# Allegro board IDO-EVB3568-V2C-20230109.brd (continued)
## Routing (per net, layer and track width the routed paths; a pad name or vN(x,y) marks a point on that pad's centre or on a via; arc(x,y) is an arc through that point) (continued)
WIFI1T1R_CMD: length 2.2
  TOP w0.127: U18.16 107.66,26.54 R186.2
WIFI1T1R_D0: length 2.4
  TOP w0.127: U18.18 105.86,24.73 105.59,24.99 105.59,26.4 R181.2
WIFI1T1R_D1: length 2.4
  TOP w0.127: R182.2 104.62,26.45 104.62,25.7 104.96,25.37 U18.19
WIFI1T1R_D2: length 2.4
  TOP w0.127: R183.2 109.3,26.25 109.3,25.35 109.46,25.19 U18.14
WIFI1T1R_D3: length 2.4
  TOP w0.127: R184.2 108.66,25.98 108.41,25.73 108.41,25.37 108.56,25.22 U18.15
WIFI1T1R_XTAL_IN: length 8.4
  TOP w0.254: U18.10 112.9,22.22 113.36,22.68 114.69,22.68 C114.1 115.7,23.76 117.04,25.1 117.04,26.24 XT2.3
WIFI1T1R_XTAL_OUT: length 2.1
  TOP w0.254: R191.2 113.87,23.12 U18.11
WIFI_PWREN_L_GPIO0_B7: length 114.9
  TOP w0.127: v1(123.44,42.55) 123.44,40.28 125.78,37.95 125.78,35.04 R207.2 ; J2.114 57.92,52.46 57.61,52.15 56.65,52.15 53.19,48.68 53.19,46.46 53.6,46.04 53.6,45.25 53.44,45.09 53.44,44.83 v1(53.42,44.81)
  BOTTOM w0.127: v1(123.44,42.55) 123.14,42.24 122.38,42.24 121.49,43.13 113.11,43.13 108.79,38.81 105.87,38.81 105.11,38.05 99.64,38.05 99.26,37.67 97.8,37.67 95.3,40.16 95.01,40.46 77.42,40.46 75.26,38.3 74.24,38.3 73.23,37.29 73.23,36.35 66.55,29.67 57.35,29.67 56.59,30.43 53.29,30.43 52.27,31.45 52.27,41.38 53.43,42.54 53.43,44.79 v1(53.42,44.81)
WIFI_REG_ON_H_GPIO3_D5: length 86.9
  TOP w0.127: R196.1 v1(110.85,28.02) 110.85,28.88 108.28,31.45 106.75,31.45 97.35,31.45 97.16,31.64 97.16,42.37 97.35,42.56 v1(97.35,42.65) ; v1(101.55,11.07) 101.73,11.07 102.08,10.72 102.08,9.89 R210.1 ; v1(77.29,60.17) 77.32,60.15 77.67,60.15 78.17,60.65 J2.33
  BOTTOM w0.127: v1(110.85,28.02) 110.21,28.02 106.55,24.36 106.55,17.65 101.55,12.65 v1(101.55,11.07) ; v1(77.29,60.17) 77.55,59.92 77.55,55.62 78.41,54.76 78.41,51.92 79.32,51 79.32,49.23 79.07,48.97 79.07,46.94 83.01,43 96.22,43 96.49,42.72 97.26,42.72 97.33,42.65 v1(97.35,42.65)
WIFI_WAKE_HOST_H_GPIO3_D4: length 70.1
  TOP w0.127: v1(79.68,62.73) 79.68,62.74 79.5,62.74 79.17,62.41 J2.29 ; U18.13 110.36,28.99 108.15,31.19 106.65,31.19 106.65,31.19 105.6,31.19 105.6,31.19 97.24,31.19 96.88,31.56 96.88,43.32 v1(97.15,43.59)
  BOTTOM w0.127: v1(79.68,62.73) 79.19,62.73 77.8,61.34 77.8,55.73 78.66,54.86 78.66,52.04 79.58,51.13 79.58,49.1 79.32,48.84 79.32,47.07 83.13,43.26 96.82,43.26 97.15,43.58 v1(97.15,43.59)
WIFIBT_32KIN_1T1R: length 5.2
  TOP w0.127: U18.24 100.24,22.22 99.77,22.68 C126.2 R204.2 R206.2 R205.2
N17053074: length 3.4
  TOP w0.508: U18.2 C115.2 115.82,15.02 C113.2
N17053234: length 3
  TOP w0.508: J21.2 arc(118.81,14.99) C116.2 arc(117.33,15.01) C113.1
N68563646: length 5.3
  TOP w0.127: U21.1 76.77,32.65 C179.2 77.17,32.02 77.17,30.18 77.04,30.05 XT5.2
N68563661: length 5.5
  TOP w0.127: U21.2 77.42,33.03 C180.2 77.42,32.02 77.42,30.18 77.55,30.05 XT5.1
N69811939: length 4.2
  TOP w0.254: U1.5 69.29,67.89 69.67,67.51 69.67,67.07 69.42,66.82 C12.2 R5.2 71,67.01 R3.1
N69812073: length 0.9
  TOP w0.305: 66.64,65.84 C1.1
N69812091: length 1.8
  TOP w0.305: C1.2 68.45,66.54 69.02,67.11 U1.4
N69812134: length 4.2
  TOP w0.305: U1.6 70,68.39 R4.1
  TOP w0.381: R6.2 R4.1 C8.1
N69812831: length 3.2
  TOP w0.381: C13.1 17.99,25.51 17.27,24.79 16.59,24.79 16.23,25.15
N69812843: length 4
  TOP w0.305: 20.4,28.14 20.02,28.52 U2.6
  TOP w0.381: 20.4,28.14 21.03,27.51 C17.1 R11.1 R12.2
N69812998: length 1.4
  TOP w0.305: C13.2 19.61,27.07 U2.4
N69813915: length 5.1
  TOP w0.127: R13.2 20.4,24.71 20.14,24.97 20.14,25.86 20.52,26.24 20.52,27.38 19.89,28.02 U2.5
N69814410: length 3.3
  TOP w0.381: R15.1 25.61,24.27 U3.5 ; R15.1 C24.1 ; R15.1 R16.2
N69814930: length 1.7
  TOP w0.203: U3.1 29.55,24.27 30.68,23.14 R14.2
N69815076: length 5.7
  TOP w0.127: 76.28,81.48 76.06,81.26 76.06,76.6 76.25,76.4 R10.2
N69815079: length 6.7
  TOP w0.127: R8.2 76.53,80.21 77.29,80.98 77.29,83.01 LED1.1
N69817092: length 6.3
  TOP w0.127: R25.2 54.72,65.68 D5.2 54.06,66.33 54.06,66.51 54.31,66.75 56.16,66.75 57.18,67.77 J4.1
N69817095: length 5.6
  TOP w0.127: J4.2 55.93,67.49 55.45,67.01 54.18,67.01 53.8,66.62 53.8,66.34 D6.2 53.13,65.68 R26.2
N69818339: length 2.8
  TOP w0.254: U8.1 104.26,34.54 103.33,33.6 R58.1
N69818343: length 2.5
  TOP w0.254: U8.7 107.26,34.11 107.01,33.86 R55.1
N69818347: length 2.6
  TOP w0.254: U8.5 106.26,34.51 105.74,33.99 R54.1
N69818991: length 4.5
  TOP w0.254: C44.2 100.27,41.45 U8.39
  TOP w0.381: C44.2 99.32,40.51 R61.1
N69818999: length 2.8
  TOP w0.254: U8.48 102.02,36.95 100.81,35.74 R59.2
N69819001: length 5.2
  TOP w0.254: U8.36 104.26,44.61 104.09,44.78 100.86,44.78 R65.2
N69819016: length 2.5
  TOP w0.254: R73.1 108.26,45.71 U8.28
N69819018: length 3.5
  TOP w0.254: C45.2 99.96,42.2 100.22,41.95 U8.38
N69820056: length 1.1
  TOP w0.381: R45.2 93.86,71.47 U5.3
N69820298: length 1.3
  TOP w0.127: U6.3 91.14,65.29 R51.2
N69820533: length 1.6
  TOP w0.127: R57.2 123.21,22.23 122.93,22.51 U7.4
N69820554: length 1.5
  TOP w0.381: R60.2 123.71,19.81 U7.3
N69820805: length 1.8
  TOP w0.127: R70.2 106.57,9.92 106.42,9.78 U9.4
N69820826: length 2.8
  TOP w0.508: U9.3 109.61,9.15 109.87,9.41 111.83,9.41 R72.2
N69821095: length 2.2
  TOP w0.127: U10.4 97.66,17.69 R77.2
N69821116: length 3.4
  TOP w0.381: U10.3 99.2,13.1 99.7,12.6 R79.2
N69821410: length 2.8
  BOTTOM w0.127: U4.4 121.93,48.93 R36.2 R32.2
N69821431: length 1.9
  BOTTOM w0.381: R33.2 123.01,53.12 122.63,53.5 U4.3
N69829177: length 5.6
  BOTTOM w0.254: Q1.1 115.89,47.93 116.4,48.44 116.92,48.44 117.42,48.95 Q2.3 117.42,49.98 117.49,50.05 R31.1 R30.1 117.5,51.1 R35.2
N69829182: length 11.2
  BOTTOM w0.381: R39.1 115.59,52.46 115.7,52.35 D13.A D11.A 118.19,54.31 117.42,55.07 R37.1 ; R37.1 117.41,57.8 R40.2 ; R37.1 117.44,57.8 R38.2
N69829189: length 15.9
  TOP w0.254: v1(112.03,53.36) 112.03,51.8 117.1,46.73 117.46,46.73 117.51,46.77 v1(117.51,46.81)
  BOTTOM w0.254: R35.1 118.52,50.06 118.19,49.73 118.19,48.34 117.92,48.07 Q2.1 117.92,47.19 117.55,46.81 v1(117.51,46.81)
  BOTTOM w0.508: R39.2 C35.2 R41.2 v1(112.03,53.36)
N69844387: length 1.9
  TOP w0.381: C63.1 128.82,60.91 127.86,60.91 R80.2 R83.2
N69844453: length 6.5
  TOP w0.203: J11.1 126.44,65.23 127.15,64.51 D29.2 127.2,63.65 127.2,62.71 C65.2 127.01,62.51 127.01,61.85 R83.1 126.49,61.77 126.14,61.42 C64.1
N69844782: length 10.9
  TOP w0.203: J10.2 121.11,83.78 121.11,83.26 119.84,81.99 119.84,77.04 120.6,76.28 D27.2 120.57,75.84 R82.2
N69844789: length 3.3
  TOP w0.203: R84.2 116.76,75.84 D28.2 116.79,77.26 J10.3
N69846177: length 0.9
  TOP w0.203: R87.1 C72.1
N69846180: length 16
  TOP w0.254: U11.7 113.41,65.48 114.3,64.59 115.75,64.59 116.38,65.23 116.38,66.88 116.23,67.03 116.23,72.19 116.69,72.64 116.69,73.41 116.43,73.66 115.47,73.66 114,75.13 R87.2
N69846237: length 0.9
  TOP w0.203: R88.1 C75.1
N69846239: length 12.6
  TOP w0.203: R88.2 117.81,74.5 117.08,73.77 117.08,72.48 116.59,71.98 116.59,67.21 116.76,67.03 116.76,65.51 117.3,64.97 117.68,64.97 118.19,65.48 118.95,65.48
N69846282: length 1.9
  TOP w0.381: C71.2 111.14,64.21 U11.8
N69846442: length 31.7
  TOP w0.127: Q14.3 85.69,65.54 86.76,64.47 v1(86.76,63.58) ; U11.5 112.22,68.02 v1(111.71,68.53)
  BOTTOM w0.127: v1(111.71,68.53) 111.71,68.25 109.07,65.61 103.23,65.61 102.34,64.72 96.06,64.72 94.56,63.22 87.12,63.22 v1(86.76,63.58)
N69846447: length 40.7
  TOP w0.127: v1(117.68,67.89) 117.81,68.02 118.95,68.02 ; Q15.3 84.11,65.62 85.2,64.53 85.2,63.33 85.23,63.31 v1(85.23,63.28)
  BOTTOM w0.127: v1(85.23,63.28) 85.55,62.97 94.69,62.97 96.19,64.47 102.46,64.47 103.35,65.35 109.19,65.35 111.99,68.15 117.42,68.15 v1(117.68,67.89)
N69846810: length 2.1
  TOP w0.381: U11.3 111.27,70.56 L11.1
N69846813: length 2.3
  TOP w0.381: L12.1 111.65,73.1 U11.1
N69846816: length 2.4
  TOP w0.203: L13.1 120.22,71.2 119.58,70.56 118.95,70.56
N69846819: length 2.3
  TOP w0.203: L14.1 120.09,72.59 119.58,73.1 118.95,73.1
N69847759: length 6.8
  TOP w0.254: D42.C 73.71,71.65 73.25,71.65 72.85,71.25 71.32,71.25 v1(71.3,71.27) ; R104.2 v1(69.04,70.97)
  TOP w0.305: R106.1 71.17,71.4 v1(71.3,71.27)
  BOTTOM w0.254: v1(69.04,70.97) 69.44,71.37 71.07,71.37 71.15,71.3 71.27,71.3 v1(71.3,71.27)
N69853352: length 4.1
  BOTTOM w0.127: R392.2 22,52.56 22.28,52.28 22.28,50.33 22.22,50.27 21.82,50.27 21.41,49.86 Q13.3
N69854514: length 0.9
  BOTTOM w0.127: Q13.1 20.82,50.79 20.07,50.79 R393.1
N69857283: length 3
  TOP w0.381: R172.1 R173.2 54.81,21.41 55.07,21.67 55.32,21.67 55.73,22.08 U15.4
N69857307: length 3.7
  TOP w0.381: R175.1 60.91,21.54 60.85,21.6 U16.4 ; R175.1 C108.2 ; R175.1 R176.2
N69857397: length 3
  TOP w0.381: U17.4 66.38,21.67 66.12,21.41 R179.2 R177.1
N69863572: length 2.3
  TOP w0.254: R191.1 C117.2 115.55,25.53 XT2.1
N69863896: length 4.2
  TOP w0.127: U18.34 102.26,12.59 100.69,11.02 R209.2 R210.2
N69864199: length 1.9
  TOP w0.381: R208.2 99.87,17.76 99.91,17.72 U18.29
N69864441: length 2.4
  TOP w0.127: U18.12 111.26,25.29 110.85,25.7 R196.2
N69864462: length 6.5
  TOP w0.508: C128.2 v1(99.77,23.7) 100.35,23.12 U18.23
  BOTTOM w0.508: v1(99.77,23.7) 99.9,23.83 v1(99.9,27.13) v1(99.9,27.89)
N69866041: length 3.3
  TOP w0.508: R207.1 R203.1 124.41,33.22 124.52,33.11 C124.1 123.34,32.72 Q10.1
N69873113: length 7.6
  TOP w0.381: C142.2 33.1,71.96 v1(33.22,72.09)
  BOTTOM w0.508: J22.1 32.97,72.34 v1(33.22,72.09)
N69883193: length 8.9
  TOP w0.508: C166.2 50.67,68.55 50.67,73.2 v1(51.12,73.65)
  BOTTOM w0.508: v1(51.12,73.65) 49.81,72.34 J23.1
N69887530: length 3.9
  BOTTOM w0.127: R345.2 96.98,54.24
  BOTTOM w0.508: R343.1 C207.1 ; C207.1 97.92,53.35 98.43,52.84 U22.5 ; C207.1 96.98,54.24
N69887600: length 1.4
  BOTTOM w0.127: R344.2 101.55,52.89 U22.1
N69896427: length 2.5
  TOP w0.508: J26.8 116.9,52 116.41,51.51 R333.1
N69897118: length 3.5
  TOP w0.508: J26.22 108.1,52.15 108.61,51.64 109.17,51.64 109.68,51.13 R337.1
N69899428: length 34.1
  TOP w0.305: J26.42 100.1,55.3 100.61,55.8 107.85,55.8 108.41,55.24 109.65,55.24 110.69,54.2 110.69,50.27 115.01,45.95 115.01,45.95 v1(115.04,45.91) ; LED2.2 123.19,48.37 122.61,47.79 v1(122.61,47.34)
  BOTTOM w0.305: v1(122.61,47.34) 122.61,46.79 121.62,45.8 115.16,45.8 v1(115.04,45.91)
N69899460: length 3
  TOP w0.508: R342.1 122.57,49.79 122.76,49.97 LED2.1
N69910248: length 16.6
  TOP w0.127: v1(128.6,86.69) 128.47,86.82 122.89,86.82 122,85.93 122,83.03 120.9,81.94 120.9,81.1 122.22,79.78 D71.1 122.22,78.59 R330.2
  BOTTOM w0.127: v1(128.6,86.69) 128.88,86.41 SW1.3
N69911722: length 4.1
  TOP w0.508: U12.3 88.28,24.65 89.97,22.96 R99.2
N69911786: length 10.2
  TOP w0.254: 85.04,9.86 J13.17
  TOP w0.508: 85.04,9.86 85.04,10.24 85.8,11 89.81,11 90.32,11.51 C78.2 90.32,13.4 R413.2 R415.2
N69922645: length 2
  TOP w0.508: R117.2 30.49,17.42 U13.3
N69927197: length 1.7
  TOP w0.381: Q8.3 28.23,10.91 28.42,10.72 28.42,10.08 R136.2
N69927388: length 1.1
  TOP w0.305: Q8.1 30.86,11.13 R137.1
N70033042: length 1.5
  TOP w0.127: Q15.1 81.85,64.53 81.72,64.66 R89.2
N70033056: length 1.4
  TOP w0.127: Q14.1 84.72,64.25 84.31,64.66 R90.2
N70059784: length 7.5
  TOP w0.381: v1(20.4,30.28) 20.4,29.57 C258.2 21.18,29.54 R409.2 R408.2
  BOTTOM w0.305: v1(20.4,30.28) 20.4,33.2 20.09,33.51 J15.17
N70064377: length 26.8
  TOP w0.127: v1(88.24,85.42) 85.06,82.25 81.99,82.25 80.31,80.57 78.82,80.57 77.29,79.04 77.29,72.92 77.01,72.64 75.93,72.64 75.69,72.41 75.69,71.7 76.3,71.09 D96.1 76.3,70.49 76.53,70.27 76.53,69.08 76.47,69.02 R412.2
  BOTTOM w0.127: SW2.3 88.24,86.33 v1(88.24,85.42)

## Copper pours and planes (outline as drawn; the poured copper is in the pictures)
GND on TOP (solid shape): 36.54,38.51 36.44,38.51 36.35,38.41 32.95,38.41 32.95,42.06 36.54,42.06
GND on TOP (solid shape): 61.82,38.28 58.22,38.28 58.22,41.88 58.52,41.88 58.52,41.93 61.82,41.93
GND on TOP (solid shape): 67.96,77.21 67.96,76.75 66.3,76.75 66.26,76.79 66.26,77.38 66.39,77.51 67.65,77.51
GND on TOP (solid shape): 12.51,17.49 12.51,17.04 11.08,17.04 10.82,17.31 10.82,17.58 12.07,17.58 12.07,17.72 12.28,17.72
GND on TOP (solid shape): 43.79,67.39 44.02,67.39 44.02,67.12 43.95,67.12 43.95,66 42.82,66 42.82,67.12 42.75,67.12 42.75,67.39 42.98,67.39 43.38,67.79
GND on TOP (solid shape): 60.37,79.02 60.37,78.66 60.36,78.65 60.19,78.65 60.19,76.79 59.8,76.79 59.8,78.65 59.63,78.65 59.63,78.88 59.97,79.22 60.17,79.22
GND on TOP (solid shape): 66.71,36.83 66.71,35.66 66.39,35.34 65.78,35.34 65.74,35.39 65.74,35.98 65.64,36.01 65.64,36.19 65.74,36.19 65.74,37.05 66.5,37.05
GND on TOP (solid shape): 33.65,34.87 34.24,34.87 34.25,34.87 34.25,33.68 34.21,33.64 33,33.64 32.85,33.78 32.85,34.83 32.9,34.87 33.48,34.87 33.48,34.97 33.65,34.97
GND on TOP (solid shape): 54.43,32.33 55.01,32.33 55.05,32.29 55.05,31.23 54.84,31.23 54.84,30.25 54.66,30.25 54.19,30.72 54.19,31.53 54.28,31.53 54.28,32.43 54.43,32.43
GND on TOP (solid shape): 41.91,68.41 41.99,68.41 41.99,68.15 41.38,68.15 41.38,68.19 41.37,68.26 41.35,68.33 41.35,68.39 41.41,68.39 41.41,69.8 41.91,69.8
GND on TOP (solid shape): 61.86,79.03 61.86,78.85 61.74,78.73 61.74,78.65 61.69,78.65 61.69,76.79 61.3,76.79 61.3,78.65 61.14,78.65 61.13,78.66 61.13,79.02 61.33,79.22 61.67,79.22
GND on TOP (solid shape): 43.6,39.35 43.6,38.57 42.61,38.57 42.49,38.69 42.49,39.35 43.3,39.35 43.3,39.56 43.6,39.56
GND on TOP (solid shape): 63.37,79.02 63.37,78.84 63.24,78.71 63.24,78.65 63.19,78.65 63.19,76.79 62.8,76.79 62.8,78.65 62.75,78.65 62.75,78.73 62.62,78.85 62.62,79 62.84,79.22 63.17,79.22
GND on TOP (solid shape): 77.29,17.4 77.35,17.49 77.47,17.47 77.93,17.01 77.93,14.56 77.42,14.56 77.29,14.69
GND on TOP (solid shape): 13.07,17.91 14.45,17.91 14.45,17.81 14.41,17.81 14.31,17.78 14.22,17.74 13.02,17.74 12.51,18.25 12.07,18.25 12.07,18.39 10.82,18.39 10.82,18.79 10.96,18.92 12.06,18.92
GND on TOP (solid shape): 28.13,56.1 28.07,56.03 27.75,56.35 26.92,56.35 26.83,56.41 26.85,56.52 27.27,56.94 27.27,60.37 28.13,60.37
GND on TOP (solid shape): 29.27,43.97 29.27,43.8 29.46,43.61 29.46,42.74 29.4,42.65 29.29,42.67 29.25,42.71 28.54,42.71 28.54,43.92 28.56,43.92 28.56,44.11 29.13,44.11
GND on TOP (solid shape): 43.98,12.56 44.03,12.53 44.02,12.47 44,12.45 44,12.23 43.96,12.23 43.96,10.27 44,10.27 44,10.01 43.71,9.72 43.53,9.91 43.53,10.27 43.57,10.27 43.57,12.26 43.87,12.56
GND on TOP (solid shape): 98.62,25.07 98.6,25.07 98.6,24.97 98.5,24.97 98.5,24.21 98.6,24.21 98.6,24.08 98.5,24.08 98.5,23.32 98.6,23.32 98.6,23.06 98.5,23.06 98.5,22.3 98.6,22.3 98.6,22.14 97.73,22.14 97.28,22.59 97.28,25.07 97.4,25.18 98.62,25.18
GND on TOP (solid shape): 101.04,73.98 101.13,73.91 101.11,73.8 100.74,73.43 100.74,73.32 100.7,73.32 100.7,71.67 100.63,71.59 100.31,71.59 100.31,73.32 100.27,73.32 100.27,73.74 100.52,73.98
GND on TOP (solid shape): 109.79,11.78 109.79,10.6 109.69,10.5 109.29,10.5 109.26,10.47 109.2,10.46 109.17,10.51 109.17,11.25 109.07,11.25 109.07,11.35 108.86,11.35 108.86,11.62 108.82,11.65 108.82,12.11 109.45,12.11
GND on TOP (solid shape): 48.83,14.7 48.79,14.62 48.76,14.53 48.75,14.51 48.57,14.33 47.42,14.33 47.42,14.42 46.46,14.42 46.46,13.52 46.3,13.52 46.3,13.61 45.69,13.61 45.69,14.4 45.68,14.41 45.68,14.57 45.78,14.67 46.98,14.67 47.4,15.09 48.83,15.09
GND on TOP (solid shape): 80.86,17.11 80.92,17.21 81.03,17.18 81.1,17.12 81.1,13.43 81.6,12.94 81.48,12.82 81.48,12.74 81.43,12.74 81.43,10.74 81.03,10.74 81.03,12.74 80.86,12.74 80.86,12.74
GND on TOP (solid shape): 107.59,73.93 107.69,73.86 107.67,73.75 107.23,73.32 107.21,73.32 107.21,71.36 107.24,71.36 107.24,70.96 107.02,70.96 107.02,71.46 106.81,71.67 106.81,73.32 106.78,73.32 106.78,73.76 106.94,73.93
GND on TOP (solid shape): 26.71,43.92 27.48,43.92 27.48,43.1 27.58,43.1 27.58,42.95 27.48,42.95 27.48,42.11 26.9,42.11 26.25,42.76 26.25,43.84 26.29,43.92 26.38,43.94 26.5,43.92 26.63,43.94 26.63,43.94 26.71,43.94
GND on TOP (solid shape): 33.39,52.11 33.87,51.63 34,51.63 34.76,50.86 35.2,50.86 35.25,50.81 35.27,50.7 35.18,50.63 34.26,50.63 34.26,50.88 34.16,50.88 34.16,50.98 33.32,50.98 33.32,51.78 33.19,51.78 33.19,52.17 33.25,52.17
GND on TOP (solid shape): 85.26,54.5 85.29,54.39 85.19,54.33 81.59,54.33 81.59,54.28 81.25,54.28 81.25,54.33 80.69,54.33 80.68,54.71 80.71,54.78 80.78,54.81 84.96,54.81
GND on TOP (solid shape): 31.86,46.31 31.98,46.23 32.11,46.19 32.16,46.18 32.16,46.07 32.56,45.67 32.62,45.67 32.62,45.03 31.8,45.03 31.8,45.84 31.56,45.84 31.47,45.9 31.49,46.01 31.82,46.34
GND on TOP (solid shape): 59.16,51.87 59.19,51.83 59.19,51.5 59.12,51.42 59.12,51.3 58.91,51.3 58.91,50.5 58.12,50.5 58.12,50.44 57.51,50.44 57.29,50.66 56.54,50.66 56.45,50.73 56.47,50.84 56.55,50.91 57.39,50.91 58.65,52.17 59.16,52.17
GND on TOP (solid shape): 120.55,81.64 120.61,81.65 120.64,81.6 120.64,80.99 121.73,79.89 121.73,79.19 121.96,79.19 121.96,79.04 120.81,79.04 120.81,77.32 120.75,77.22 120.64,77.24 120.52,77.36 120.52,81.61
GND on TOP (solid shape): 38.99,70.02 39.02,69.91 38.92,69.85 38.5,69.85 38.5,68.39 38.56,68.39 38.56,68.33 38.54,68.26 38.53,68.19 38.52,68.15 37.92,68.15 37.92,68.41 37.99,68.41 37.99,69.72 37.29,69.72 37.29,70.6 37.37,70.69 38.32,70.69
GND on TOP (solid shape): 45.09,52.17 45.23,52.17 45.36,52.07 46.16,51.27 46.16,50.76 46.1,50.66 45.99,50.69 44.67,52 44.65,52.11 44.75,52.17 44.75,52.17 44.75,54.29 45.09,54.29
GND on TOP (solid shape): 49.82,36.29 49.82,30.52 50.23,30.12 50.23,28.77 50.51,28.49 50.5,28.46 50.51,28.31 50.56,28.16 50.58,28.13 47.87,25.42 47.76,25.4 47.7,25.49 47.7,25.88 48.74,26.92 48.74,37.2 48.91,37.2
GND on TOP (solid shape): 121.92,40.78 122.04,40.8 122.1,40.7 122.1,39.64 123.01,38.73 123.01,38.4 122.98,38.4 122.98,38.31 122.98,38.3 122.89,38.3 122.89,37.54 122.94,37.54 122.94,36.99 122.85,36.91 122.72,36.91 122.72,37.07 122.62,37.07 122.46,37.24 121.37,37.24 121.37,40.22
GND on TOP (solid shape): 66.71,38.38 66.71,38.29 66.71,38.2 66.71,38.2 66.71,37.58 65.82,37.58 65.74,37.66 65.74,38.18 65.64,38.18 65.64,38.27 65.06,38.27 65.03,38.3 65.02,38.35 65.07,38.38 66.54,38.38 66.54,38.6 66.71,38.6
GND on TOP (solid shape): 97.42,34.23 97.48,34.32 97.6,34.3 98.3,33.59 98.3,32.14 98.29,32.13 98.26,31.99 98.27,31.84 98.26,31.75 98.18,31.71 97.46,31.71 97.42,31.75
GND on TOP (solid shape): 47.38,59.14 47.41,59.13 47.53,59.05 47.68,59 47.72,59 47.72,58.92 46.03,57.23 45.91,57.23 45.87,57.26 45.88,57.32 47.07,58.52 47.07,59.02 47.11,59.02 47.24,59.06 47.34,59.13
GND on TOP (solid shape): 50.2,59.17 50.23,59.16 50.33,59.11 50.43,59.07 50.48,59.07 50.48,58.97 47.26,55.76 47.19,55.76 47.15,55.79 47.16,55.85 49.84,58.53 49.84,59.01 49.89,59.02 50.04,59.06 50.17,59.16
GND on TOP (solid shape): 73.84,60.37 74.63,60.37 74.7,59.95 74.67,59.87 74.6,59.83 73.51,59.83 73.43,59.87 73.42,59.97 73.45,60.11 73.44,60.25 73.44,60.26 73.44,60.37 73.5,60.37 73.5,62.29 73.84,62.29
GND on TOP (solid shape): 77.44,29.78 77.96,29.78 77.96,29.04 79.1,29.04 79.19,28.98 79.17,28.87 77.79,27.49 77.79,23.44 77.72,23.35 77.61,23.37 75.48,25.51 75.48,29.04 76.72,29.04 76.72,29.78 77.15,29.78 77.29,29.92
GND on TOP (solid shape): 102.21,47.42 102.21,46.71 102.06,46.71 102.06,46.81 101.3,46.81 101.3,46.71 101.2,46.71 101.2,45.8 100.57,45.8 100.57,45.94 98.72,45.94 98.72,45.82 98.4,45.5 98.38,45.5 98.27,45.49 98.17,45.45 98.07,45.45 98.02,45.54 98.02,45.57 100,47.55 102.08,47.55
GND on TOP (solid shape): 17.68,21.44 17.74,21.53 17.85,21.51 18.03,21.34 22.86,21.34 22.86,21.15 23.11,20.9 23.13,20.79 23.03,20.73 21.84,20.73 21.73,20.62 21.59,20.62 21.59,18.95 18.55,18.95 18.31,19.19 18.31,20.71 17.68,21.35
GND on TOP (solid shape): 48.8,59.14 48.83,59.13 48.93,59.07 49.04,59.03 49.08,59.02 49.08,58.85 46.73,56.5 46.62,56.5 46.53,56.56 46.55,56.67 48.48,58.6 48.48,59 48.52,59.01 48.65,59.05 48.77,59.13
GND on TOP (solid shape): 66.81,19.39 67.76,19.39 67.76,19.66 68.25,20.14 68.78,20.14 68.78,20.24 68.89,20.24 68.89,20.11 69.69,20.11 69.98,19.83 69.98,18.93 69.34,18.3 69.34,17.2 69.28,17.1 69.17,17.13 67.75,18.54 66.15,18.54 65.81,18.88 65.81,20.19 66.5,20.19 66.5,20.29 66.59,20.29 66.59,20.38 66.81,20.38
GND on TOP (solid shape): 72.25,54.1 72.31,54.19 72.42,54.17 72.54,54.06 72.59,52.37 72.59,52.17 73.16,52.17 73.16,51.21 74.45,49.92 75.06,49.92 75.06,49.18 75,49.09 74.89,49.11 72.19,51.81 72.19,52.23 72.26,52.32 72.25,52.39
GND on TOP (solid shape): 116.74,38.78 116.74,38.64 116.68,38.55 116.57,38.57 115.43,39.71 114.67,39.71 114.63,39.75 114.63,40.34 114.53,40.34 114.53,40.43 113.57,40.43 113.57,40.35 113.2,40.35 113.15,40.3 113.12,40.28 112.99,40.28 112.95,40.31 112.96,40.37 113.31,40.72 114.8,40.72
GND on TOP (solid shape): 16.57,13.17 18.14,11.61 18.15,11.55 18.11,11.52 18.05,11.52 17.54,11.01 15.08,11.01 14.91,11.17 14.68,11.22 14.65,11.24 14.63,11.27 14.63,12.76 15.48,12.76 15.48,14.67 15.87,15.07 15.87,15.34 16.24,15.34 16.24,15.43 16.57,15.43
GND on TOP (solid shape): 48.64,11.51 47.83,11.51 47.83,11.46 47.74,11.46 47.7,11.41 47.57,11.41 47.57,11.51 46.79,11.51 46.74,11.41 46.56,11.41 46.56,11.51 45.8,11.51 45.8,11.41 45.7,11.41 45.7,10.8 45.64,10.75 45.59,10.73 45.54,10.72 45.45,10.73 45.4,10.81 45.4,11.62 46.19,12.41 46.19,12.56 47.42,12.56 47.42,12.77 48.64,12.77
GND on TOP (solid shape): 57.33,67.35 57.42,67.29 57.4,67.17 56.96,66.73 56.96,63.84 56.91,63.75 56.81,63.75 56.77,63.77 56.71,63.79 56.18,64.31 56.18,66.16 55.22,66.16 55.22,65.94 55.07,65.94 55.07,66.32 54.45,66.32 54.35,66.42 54.42,66.48 56.27,66.48 57.13,67.35
GND on TOP (solid shape): 61.04,31.53 61.15,31.55 61.21,31.46 61.21,29.56 61.61,29.16 62.31,29.16 62.5,29.34 63.19,29.34 64.21,28.32 64.21,27.95 64.15,27.86 64.04,27.88 63.48,28.44 55.9,28.44 55.52,28.06 55.33,28.06 55.33,28.67 55.69,29.02 58.99,29.02 60.41,30.45 60.41,30.9
GND on TOP (solid shape): 63.34,13.21 63.42,13.16 63.48,13.08 63.56,13.01 63.56,12.87 63.52,12.87 63.52,10.91 63.56,10.91 63.56,10.59 63.26,10.3 63.15,10.28 63.09,10.37 63.09,10.91 63.13,10.91 63.13,12.87 63.12,12.87 63.09,12.93 63.21,13.05 63.21,13.14 63.26,13.18
GND on TOP (solid shape): 126,49.93 127.18,49.93 127.18,49.88 127.42,49.65 127.44,49.54 127.35,49.48 126.05,49.48 126.05,49.34 125.7,49.34 125.61,49.4 125.63,49.51 125.75,49.7 125.77,49.93 125.77,49.95 125.88,50.06 126,50.06
GND on TOP (solid shape): 70.4,70.95 70.52,70.82 70.52,69.42 69.85,68.75 69.02,68.75 68.96,68.74 68.89,68.73 68.58,68.73 68.58,67.17 68.09,66.69 68.09,66.32 67.11,66.32 67.11,67.33 67.29,67.51 67.83,67.51 67.87,67.56 67.97,67.56 67.97,67.66 68,67.68 68,68.08 67.97,68.1 67.97,68.14 68.07,68.24 68.07,68.65 68.08,68.66 68.08,68.84 68.1,68.84 68.1,68.94 68.2,68.94 68.2,69.6 69.05,69.6 69.93,70.48 69.93,71.09 70.17,71.33 70.4,71.33
GND on TOP (solid shape): 121.14,75.36 121.23,75.36 121.23,75.26 121.95,75.26 121.95,74.3 122.13,74.11 122.13,74.09 122.13,74.01 122.15,73.93 122.13,73.84 122.05,73.8 121.29,73.8 120.96,74.13 120.15,74.13 120.07,74.17 120.05,74.26 120.06,74.33 120.06,74.46 120.06,75.38 121.14,75.38
GND on TOP (solid shape): 45.07,18.05 45.16,18 45.15,17.89 44.93,17.36 45.03,16.8 45.03,16.71 44.97,16.66 44.89,16.62 44.79,16.72 44.09,16.72 44.09,17.13 45.01,18.05
GND on TOP (solid shape): 67.82,75.85 67.82,74.85 67.93,74.85 68.03,74.79 68,74.67 67.83,74.5 67.32,74.5 67.32,73.25 67.52,73.25 67.52,71.8 67.45,71.71 67.34,71.73 67.16,71.92 67.16,74.91 66.29,75.79 66.26,75.9 66.36,75.96 67.71,75.96
GND on TOP (solid shape): 29.13,60.3 29.15,60.29 29.15,57.24 29.81,56.58 29.84,56.48 29.77,56.41 29.63,56.34 29.52,56.22 29.3,56.22 29.11,56.03 29.02,56 28.95,56.05 28.84,56.19 28.7,56.28 28.66,56.29 28.66,60.29 28.7,60.33 28.83,60.37 29,60.37
GND on TOP (solid shape): 68.1,80.3 68.17,80.39 68.28,80.37 69.73,78.92 71.05,78.92 71.25,78.72 71.28,78.63 71.23,78.55 71.14,78.5 71.07,78.42 70.41,78.42 70.41,77.55 70.28,77.55 70.28,77.65 69.52,77.65 69.52,77.55 69.42,77.55 69.42,77.5 68.75,77.5 68.75,77.53 68.47,77.81 68.47,78.39 68.02,78.84 68.02,79.22 68.1,79.22
GND on TOP (solid shape): 37.65,38.28 37.71,38.37 37.82,38.35 38.35,37.82 38.77,37.82 38.77,37.27 38.73,37.19 38.65,37.17 38.41,37.16 38.21,37.03 38.2,37.02 38.13,37.02 38.13,37.12 37.31,37.93 37.29,38.04 37.38,38.1 37.65,38.1
GND on TOP (solid shape): 73.99,44.56 74.02,44.61 74.08,44.6 74.1,44.57 74.1,43.91 74.41,43.6 74.41,43.58 74.44,43.32 74.6,43.12 74.65,43.05 74.62,42.96 74.13,42.48 74.13,40.71 74.86,39.98 74.86,39.84 74.51,39.84 74.16,39.49 74.05,39.47 73.99,39.56
GND on TOP (solid shape): 30.22,14.04 31.29,14.04 31.39,13.98 31.36,13.86 31.27,13.74 31.23,13.59 31.22,13.55 30.22,13.55 30.22,13.48 30.15,13.39 30.04,13.41 29.4,14.06 29.37,14.06 29.37,14.2 28.1,14.2 28.01,14.26 28.03,14.37 28.33,14.67 30.22,14.67
GND on TOP (solid shape): 87.61,51.52 87.88,51.33 88.2,51.35 88.3,51.34 88.34,51.26 88.34,42.73 88.24,42.62 86.2,42.62 85.8,42.22 85.8,41.37 86.2,40.97 88.21,40.97 88.21,40.84 85.97,40.84 85.73,40.6 85.62,40.58 85.56,40.68 85.56,42.35 84.8,43.11 84.8,48.86 87.46,51.52
GND on TOP (solid shape): 27.75,55.59 27.75,55.33 27.7,55.24 27.6,55.24 27.07,55.17 26.93,54.65 26.94,54.62 26.65,54.33 25.64,54.33 25.56,54.37 25.54,54.45 25.55,54.53 25.54,54.6 25.54,54.63 26.73,55.82 27.52,55.82
GND on TOP (solid shape): 33.4,23.24 34.21,23.24 34.21,23 34.44,22.77 34.47,22.7 34.44,22.62 34.32,22.48 34.27,22.29 34.27,22.25 32.29,22.25 32.04,21.99 31.38,21.99 31.38,21.41 31.22,21.25 30.99,21.25 30.99,21.75 31.16,21.75 31.16,23.27 31.22,23.37 31.33,23.34 31.44,23.24 32.29,23.24 32.43,23.38 32.47,23.38 32.47,23.42 32.54,23.49 32.54,23.57 33.4,23.57
GND on TOP (solid shape): 84.87,74.34 84.95,74.37 85.03,74.33 85.09,74.26 85.16,74.2 85.2,74.13 85.17,74.05 85,73.87 85,73.6 84.83,73.6 84.83,71.64 85.01,71.64 85.01,71.43 85.16,71.28 85.16,71.2 84.72,71.2 84.72,70.73 84.52,70.73 84.52,71.15 84.34,71.15 84.25,71.21 84.26,71.32 84.26,71.64 84.44,71.64 84.44,73.6 84.28,73.6 84.28,73.76
GND on TOP (solid shape): 60.09,52.39 60.08,52.32 60.17,52.22 60.17,52.1 60.29,51.98 60.29,51.59 60.77,51.11 60.8,51.03 60.75,50.95 60.72,50.93 60.69,50.91 60.66,50.89 60.62,50.91 60.33,51.02 60.03,50.93 59.92,50.92 59.86,51.01 59.86,51.3 59.73,51.3 59.73,52.05 59.69,52.09 59.69,52.23 59.76,52.32 59.75,52.39 59.75,54.29 60.09,54.29
GND on TOP (solid shape): 85.57,65.04 85.63,65.13 85.74,65.11 86.5,64.36 86.5,63.97 86.32,63.75 86.3,63.46 86.28,63.37 86.2,63.33 85.71,63.33 85.7,63.38 85.62,63.56 85.47,63.7 85.47,64.64 85.37,64.74 85.35,64.85 85.44,64.92 85.57,64.92
GND on TOP (solid shape): 39.74,55.49 39.83,55.5 39.86,55.5 40.85,54.5 40.87,54.39 40.78,54.33 39.59,54.33 39.59,52.32 39.26,52.32 39.25,52.39 39.25,54.33 38.97,54.33 38.91,54.7 38.94,54.79 39.02,54.82 39.42,54.97 39.54,55.38 39.56,55.48 39.66,55.5
GND on TOP (solid shape): 73.79,70.78 73.81,70.67 73.73,70.6 73.55,70.54 73.41,70.41 72.86,70.43 72.66,69.91 72.64,69.83 72.56,69.79 72.38,69.79 72.38,69.87 71.58,69.87 71.58,70.48 71.77,70.48 71.94,70.65 73.08,70.65 73.31,70.88 73.69,70.88
GND on TOP (solid shape): 73.72,78.12 73.82,78.06 73.8,77.95 72.11,76.26 72.11,76.1 71.82,76.1 71.56,76.37 68.87,76.37 68.79,76.44 68.78,76.5 68.83,76.53 69.35,76.53 69.35,76.59 70.41,76.59 70.41,76.57 71.37,76.57 71.37,77.55 71.4,77.62 71.47,77.65 71.52,77.66 71.58,77.67 71.67,77.65 71.71,77.57 71.71,77.47 71.81,77.47 71.81,77.37 72.57,77.37 72.57,77.47 72.67,77.47 72.67,77.92 72.86,78.12
GND on TOP (solid shape): 81.99,64.99 82.7,64.99 82.7,65.35 84,65.35 84.04,65.31 84.06,65.2 83.97,65.14 83.29,65.14 83.29,63.66 83.09,63.46 82.57,63.46 82.43,63.6 82.24,63.67 82.2,63.67 82.2,64.65 82.11,64.65 81.83,64.93 81.4,64.93 81.4,65.18 81.53,65.51 81.4,65.83 81.38,65.94 81.48,66 81.99,66
GND on TOP (solid shape): 54.32,72.24 54.38,72.33 54.49,72.31 57.27,69.53 57.29,69.42 57.2,69.35 56.66,69.35 56.66,67.63 56.62,67.59 56.51,67.57 56.45,67.67 56.45,69.35 55.41,69.35 55.41,67.34 55.34,67.27 54.07,67.27 53.53,66.73 53.53,66.45 53.4,66.32 52.78,66.32 52.78,65.94 52.62,65.94 52.62,66.16 52.26,66.16 52.16,66.22 52.18,66.33 54.32,68.46
GND on TOP (solid shape): 76.38,37.09 76.39,37.09 76.39,36.8 76.19,36.6 76.14,36.62 76.07,36.62 76.07,37.55 75.16,37.55 75.16,36.53 75.08,36.53 75.08,35.76 75.18,35.76 75.18,35.67 75.27,35.67 75.27,35.56 74.99,35.29 74.81,35.29 74.81,34.23 75.76,34.23 75.76,33.49 74.81,33.49 74.81,32.43 74.84,32.43 74.86,32.37 74.66,32.16 74.55,32.14 74.49,32.23 74.49,38.56 74.54,38.65 74.64,38.65 74.75,38.6 74.87,38.59 74.89,38.59 74.99,38.49 75.16,38.49 75.16,38.29 76.07,38.29 76.07,39.3 76.38,39.3
GND on TOP (solid shape): 31.96,37.75 32.18,37.48 32.52,37.43 32.61,37.41 32.64,37.33 32.64,37.3 32.74,37.3 32.79,37.27 32.78,37.22 32.73,37.17 30.65,37.17 30.55,37.08 30.44,37.05 30.38,37.15 30.38,37.47 30.41,37.55 30.49,37.57 30.74,37.62 30.93,37.78 31.94,37.78
GND on TOP (solid shape): 44.49,25.21 44.49,23.96 44.48,23.95 43.93,23.95 43.6,23.62 43.41,23.62 43.4,23.67 43.27,23.93 43.01,24.07 42.94,24.12 42.93,24.21 42.95,24.26 42.96,24.31 42.96,24.36 43.11,24.36 43.51,24.76 43.51,24.83 43.54,24.87 43.59,24.86 44.08,24.79 44.38,25.18 44.38,25.22 44.48,25.22
GND on TOP (solid shape): 73.98,16.94 74.11,16.92 74.23,16.93 74.32,16.92 74.36,16.84 74.36,16.35 73.75,16.35 73.75,15.24 73.31,15.24 73.08,15.01 71.75,15.01 71.74,15 71.68,14.99 71.65,15.04 71.65,15.43 71.66,15.44 71.56,15.88 71.15,16.05 71.07,16.08 71.04,16.16 71.04,16.25 71.02,16.35 71.02,16.94 73.98,16.94
GND on TOP (solid shape): 42.48,44.57 42.54,44.58 42.57,44.53 42.57,43.05 42.46,43.05 42.46,43.41 42.37,43.41 42.37,43.51 41.61,43.51 41.61,43.41 41.51,43.41 41.51,42.7 40.67,41.86 40.67,41.35 40.43,41.11 39.83,41.11 39.83,42.75 39.81,42.75 39.78,42.81 39.87,42.9 40.36,42.9 40.36,43 40.46,43 40.46,43.63 40.5,43.71 40.96,43.84 41.13,44.2 41.16,44.27 41.23,44.3 42.03,44.3 42.03,44.51 42.43,44.51
GND on TOP (solid shape): 129.48,37.81 129.48,36.54 129.52,36.5 129.53,36.44 129.48,36.41 128.63,36.41 128.63,36.6 127.57,36.6 127.57,35.69 127.84,35.69 127.84,35.56 127.75,35.48 126.27,35.48 126.27,35.17 126.2,35.1 126.16,35.1 126.08,35.12 126.05,35.2 126.05,35.69 126.83,35.69 126.83,36.67 126.89,36.73 126.89,36.94 128,36.94 128,37.57 128.06,37.63 128.31,37.95 128.22,38.34 128.2,38.45 128.3,38.51 128.78,38.51
GND on TOP (solid shape): 32.57,18.45 32.68,18.47 32.74,18.38 32.74,17.88 33.45,17.88 33.45,18.24 33.76,18.24 34.1,17.89 34.58,17.89 34.58,17.49 34.5,17.49 34.48,17.5 34.19,17.62 33.88,17.53 33.24,17.53 33.24,16.41 32.95,16.41 32.95,16.9 32.95,16.95 32.95,17.53 32.24,17.53 32.24,16.95 32.24,16.9 32.24,16.23 31.91,15.9 31.91,15.59 31.67,15.59 31.67,14.85 30.58,14.85 30.49,14.91 30.51,15.02 32.09,16.6 32.09,17.97
GND on TOP (solid shape): 8.84,38.2 9.24,37.8 9.76,37.8 9.76,37.75 10.01,37.37 10.47,37.38 10.57,37.37 10.62,37.29 10.62,37.12 10.43,36.93 10,36.93 9.6,36.53 9.6,35.89 9.47,35.89 9.47,37.39 9.07,37.8 8.23,37.8 8.02,37.59 7.92,37.56 7.85,37.64 7.79,37.82 7.68,37.99 7.67,38.09 7.76,38.15 8.16,38.15 8.71,38.71 8.71,39.7 8.84,39.7
GND on TOP (solid shape): 94.49,79.37 94.49,77.65 94.41,77.55 94.3,77.59 93.26,78.29 92.04,77.97 91.5,78.51 91.17,78.51 91.08,78.56 91.08,78.66 91.15,79.01 91.04,79.35 91.04,79.45 91.12,79.5 94.35,79.5
GND on TOP (solid shape): 119.71,66.77 120.03,66.45 120.68,66.45 120.7,66.46 120.81,66.48 120.87,66.39 120.87,65.89 120.94,65.89 120.94,65.52 120.15,64.73 118.11,64.73 118.02,64.79 118.04,64.91 118.1,64.96 120.1,64.96 120.1,66 118.07,66 117.98,66.05 117.98,66.15 117.99,66.6 117.63,66.86 117.59,66.86 117.59,67.31 117.62,67.39 117.69,67.42 117.83,67.44 117.95,67.5 119.71,67.5
GND on TOP (solid shape): 47.21,68.44 47.3,68.4 47.31,68.3 47.29,68.06 47.4,67.83 47.43,67.77 47.4,67.7 47.3,67.49 47.3,67.26 47.3,67.25 47.3,67.2 47.26,67.2 47.26,66 46.37,66 46.37,67.2 46.32,67.2 46.32,67.25 46.32,67.26 46.33,67.49 46.22,67.7 46.2,67.77 46.22,67.83 46.33,68.06 46.31,68.3 46.33,68.4 46.41,68.44
GND on TOP (solid shape): 68.23,13.88 68.28,13.85 68.26,13.79 68.18,13.71 68.17,13.7 67.93,13.24 68.25,12.83 68.32,12.76 68.29,12.66 68.1,12.47 68.02,12.47 68.02,12.52 67.24,12.52 67.18,12.42 67.01,12.42 67.01,12.52 66.24,12.52 66.24,12.42 65.99,12.42 65.99,12.52 65.23,12.52 65.23,12.42 65.13,12.42 65.13,11.47 65.14,11.27 65.19,11.14 65.21,11.11 65.16,11.05 65.05,11.03 64.99,11.12 64.99,13.1 65.76,13.88
GND on TOP (solid shape): 52.6,22.05 52.71,22.07 52.77,21.98 52.77,18.47 52.64,18.35 52.64,17.78 52.47,17.39 52.68,17.02 52.72,16.94 52.69,16.86 51.61,15.79 51.61,15.35 51.6,15.34 51.49,15.32 51.42,15.41 51.42,16.05 51.37,16.09 51.35,16.16 51.22,16.51 50.88,16.66 50.84,16.67 50.83,16.71 50.83,20.23 50.78,20.27 50.78,20.43 51.55,20.43 51.55,21.01
GND on TOP (solid shape): 102.18,12.11 102.27,12.07 102.28,11.97 102.27,11.56 102.59,11.3 102.63,11.29 102.63,10.76 102.47,10.76 102.47,8.9 102.63,8.9 102.63,8.38 102.53,8.28 101.95,8.28 101.87,8.32 101.85,8.4 101.83,8.59 101.74,8.76 101.73,8.87 101.82,8.93 102.08,8.93 102.08,9.51 102.35,9.78 102.35,10.83 102.02,11.16 102.02,11.17 101.92,11.37 101.74,11.51 101.69,11.59 101.71,11.68 102.15,12.11
GND on TOP (solid shape): 47.98,74.9 48.04,75 48.15,74.98 49.48,73.65 49.48,71.27 49.42,71.18 49.31,71.2 49.05,71.45 48.98,71.45 48.88,71.52 48.91,71.63 49.13,72.8 48,73.19 47.92,73.19 47.87,73.25 47.85,73.29 47.85,73.36 47.96,73.36 48.34,73.73 48.34,74.48 48.06,74.75 47.98,74.86
GND on TOP (solid shape): 67.3,16.53 67.33,16.44 67.28,16.37 67.03,15.95 67.29,15.53 67.29,14.84 67.13,14.84 67.13,14.94 66.34,14.94 66.34,15.74 66.34,15.79 66.05,16.27 65.5,16.14 65.43,16.11 65.35,16.15 65.12,16.3 64.84,16.31 64.76,16.33 64.71,16.41 64.71,16.83 67,16.83
GND on TOP (solid shape): 82.59,25.77 87.42,25.77 87.91,25.28 87.93,25.17 87.84,25.11 87.5,25.11 87.5,25.15 86.04,25.15 86.04,24.14 87.5,24.14 87.5,24.19 88.09,24.19 88.84,23.44 88.86,23.33 88.77,23.27 86.22,23.27 86.21,23.25 86.04,23.25 86.04,23.08 85.98,23.02 85.98,22.97 85.92,22.88 85.81,22.9 85.75,22.96 85.75,23.51 85.1,24.16 84.8,24.16 84.8,25.15 83.3,25.15 83.3,25.45 81.64,25.45 81.54,25.51 81.57,25.62 81.67,25.75 81.73,25.91 81.76,25.97 81.83,25.99 82.02,26.01 82.18,26.11 82.22,26.14
GND on TOP (solid shape): 24,29.43 24,28.44 24.89,27.55 24.89,25.9 25.07,25.72 25.07,25.7 25.07,25.6 24.97,25.6 24.97,24.84 25.07,24.84 25.07,24.68 24.17,24.68 24.17,22.71 24.31,22.71 24.31,22.57 24.64,22.24 24.64,20.91 24.58,20.81 24.46,20.84 23.77,21.53 23.77,22.62 23.74,22.79 23.65,22.93 23.65,24.16 23.52,24.29 23.52,24.3 23.51,24.3 23.4,24.41 22.72,24.41 22.72,25.19 22.14,25.19 21.92,25.41 21.92,26.09 22.72,26.09 22.72,26.17 22.86,26.17 22.88,26.16 23.65,26.22 23.34,26.93 23.33,26.94 23.3,26.96 22.72,26.96 22.72,27.98 22.73,27.98 22.73,28 22.97,28 23.75,28.77 23.75,29.33 23.93,29.5
GND on TOP (solid shape): 49.92,52.84 50.03,52.86 50.09,52.76 50.09,52.17 50.26,52.17 50.4,52.12 50.76,51.76 50.76,50.22 49.95,49.41 49.95,49.24 49.74,49.24 49.74,47.86 49.67,47.77 49.56,47.79 49.2,48.16 49.17,48.24 49.22,48.32 49.35,49.02 48.64,49.07 48.22,49.49 48.22,51.78 48.53,52.09 48.53,52.14 48.58,52.23 48.68,52.22 49.05,52.18 49.32,52.44 49.33,52.48 49.56,52.48
GND on TOP (solid shape): 27.84,14.18 27.95,14.2 28.02,14.11 28.02,13.39 29.31,13.39 30.32,12.38 30.43,12.38 30.43,11.49 29.83,11.49 29.79,11.49 29.2,11.49 29.2,10.78 29.79,10.78 29.83,10.78 30.43,10.78 30.43,10.7 30.6,10.7 30.68,10.67 30.7,10.58 30.69,10.45 30.72,10.31 30.73,10.28 29.41,8.96 29.3,8.94 29.24,9.03 29.24,9.43 28.99,9.68 28.85,9.68 28.85,10.5 28.82,10.5 28.82,10.88 28.63,11.07 28.63,11.28 28.86,11.28 28.86,11.99 28.41,11.99 28.4,11.99 28.23,12.03 28.07,11.99 28.06,11.99 27.6,11.99 27.6,11.31 27.57,11.27 27.52,11.28 27.47,11.33 26.2,11.33 26.06,11.46 26.06,12.86 25.84,13.08 25.84,13.12 25.8,13.12 25.74,13.18 25.73,13.24 25.77,13.27 26.93,13.27
GND on TOP (solid shape): 34.59,31.79 34.63,31.87 34.72,31.89 34.74,31.89 34.94,31.69 34.96,31.69 34.96,31.6 35.05,31.6 35.05,30.53 34.96,30.53 34.96,29.57 35.89,29.57 36.33,29.13 36.54,28.93 36.84,28.89 36.92,28.87 36.96,28.79 36.96,28.44 37.97,27.42 37.97,27.06 37.87,26.95 37.78,26.92 37.71,26.98 37.66,27.05 37.59,27.11 37.59,27.63 35.89,29.34 28.75,29.34 28.67,29.41 28.66,29.47 28.71,29.5 33.57,29.5 33.57,30.98 33.7,31.11 33.74,31.12 33.77,31.11 33.83,31.06 33.89,31.02 33.89,30.4 33.99,30.4 33.99,30.3 34.75,30.3 34.75,30.4 34.84,30.4 34.84,31.36 34.69,31.36 34.62,31.39 34.59,31.46 34.58,31.55 34.55,31.64 34.54,31.72 34.59,31.77
GND on TOP (solid shape): 9.47,42.12 9.54,42.21 9.65,42.19 10.11,41.73 10.11,41.21 10.08,41.14 10.01,41.1 9.62,40.41 10.41,40.32 10.49,40.36 10.57,40.32 10.62,40.27 10.67,40.23 10.71,40.16 10.68,40.08 10.62,40.01 10.62,39.02 10.56,38.93 10.46,38.93 10.01,38.96 9.74,38.6 9.73,38.56 9.6,38.56 9.6,40.06 9.2,40.46 9.19,40.46 9.15,40.49 9.16,40.55 9.47,40.86
GND on TOP (solid shape): 27.58,26.98 27.65,27.08 27.76,27.06 27.92,26.9 28.78,26.9 28.87,26.84 28.85,26.73 28.8,26.68 28.74,26.68 28.74,26.61 28.7,26.58 28.7,25.87 28.74,25.84 28.74,25.67 28.91,25.67 28.92,25.65 30.98,25.65 31.22,25.42 31.22,23.61 30.65,23.61 30.25,24.01 30.25,24.78 28.74,24.78 28.74,23.77 29.63,23.77 30.2,23.19 30.2,22.81 30.17,22.73 30.09,22.71 29.88,22.68 29.71,22.57 29.64,22.54 29.57,22.56 29.38,22.64 29.18,22.64 29.1,22.65 29.06,22.71 28.96,22.71 28.96,22.81 28.19,22.81 28.19,22.76 27.89,22.76 27.89,22.81 27.09,22.81 26.76,22.93 26.43,22.79 26.02,22.79 26.02,23.77 27.55,23.77 27.55,24.78 26.02,24.78 26.02,25.53 27.34,25.53 27.48,25.67 27.55,25.67 27.55,25.74 27.58,25.77
GND on TOP (solid shape): 85.31,36.36 85.36,36.45 85.47,36.44 85.6,36.36 85.74,36.33 85.77,36.31 85.78,36.28 85.98,35.93 86.38,35.86 86.47,35.84 86.51,35.76 86.51,34.55 83.59,31.63 83.59,29.56 83.53,29.55 83.44,29.57 83.4,29.65 83.4,32.73 84.82,34.15 84.82,34.36 84.86,34.44 84.94,34.46 85.49,34.75 85.28,35.34 85.23,35.42 85.27,35.51 85.47,35.86 85.32,36.23 85.31,36.25
GND on TOP (solid shape): 65.45,45.66 66.89,45.66 69.74,42.82 69.74,38.79 68.42,37.48 67.77,37.48 67.77,38.1 67.67,38.1 67.67,38.2 67.67,38.2 67.67,38.29 67.67,38.48 67.77,38.48 67.77,39.24 67.67,39.24 67.67,39.34 66.71,39.34 66.71,39.13 66.54,39.13 66.54,39.34 64.82,39.34 64.36,39.8 64.34,39.91 64.43,39.98 65.48,39.98 65.59,40.08 66.12,40.08 66.12,40.18 66.21,40.18 66.21,40.71 66.24,40.73 66.43,40.73 66.75,41.05 67.47,41.05 67.99,40.52 67.99,39.3 69.6,39.3 69.6,41 68.37,41 67.74,41.64 67.77,41.7 67.8,41.7 67.8,43.4 66.19,43.4 66.19,42.24 65.35,42.24 65.35,42.14 65.26,42.14 65.26,41.62 64.63,40.99 64.02,40.99 63.94,41.03 63.93,41.12 63.93,41.42 63.75,41.67 63.71,41.74 63.74,41.82 63.76,41.85 64.02,41.85 65.57,43.4 65.57,43.76 65.79,43.98 66.37,43.98 66.37,44.94 66.27,44.94 66.27,45.03 64.61,45.03 64.61,45.84 64.05,45.84 64.05,46.81 62.96,47.89 62.93,47.99 63,48.06 63.03,48.07
GND on TOP (solid shape): 94.82,27.55 94.91,27.52 95.57,26.86 95.57,26.08 95.85,25.8 95.85,21.91 96.14,21.61 96.12,21.58 96.09,21.03 96.59,20.82 96.67,20.8 96.71,20.72 96.71,19.24 97.18,18.76 97.18,17.86 95.63,17.86 95.63,22.01 95.39,22.25 95.39,22.45 95.54,22.45 95.54,23.5 95.31,23.5 95.31,23.95 94.55,23.95 94.55,23.5 94.33,23.5 94.33,23.43 94.2,23.43 94.2,23.5 93.98,23.5 93.98,23.95 93.22,23.95 93.22,23.5 93,23.5 93,23.43 91.56,23.43 91.56,23.44 90.14,23.44 89.73,23.84 89.71,23.95 89.8,24.02 91.83,24.02 93.73,25.92 93.73,26.45 93.78,26.54 93.87,26.55 94.38,26.67 94.47,27.18 94.47,27.22 94.5,27.25 94.65,27.35 94.75,27.49
GND on TOP (solid shape): 100.07,7.48 100.14,7.45 100.22,7.38 100.99,7.38 101.38,7.22 101.74,7.42 101.85,7.46 101.92,7.37 101.92,7.31 102.56,7.31 102.7,7.17 102.7,5.49 102.31,5.1 102.31,3.68 102.25,3.59 102.15,3.6 101.07,3.42 101.31,2.35 101.36,2.23 101.26,2.16 100.74,2.16 100.64,2.22 100.66,2.33 100.74,2.4 100.74,4.1 99.34,5.49 99.34,7.26 99.39,7.35 99.48,7.36 99.76,7.33 100,7.45
GND on TOP (solid shape): 60.43,19.47 62.4,19.47 62.4,19.68 62.99,20.27 63.58,20.27 63.58,20.37 63.68,20.37 63.68,20.24 64.61,20.24 64.9,19.95 64.9,18.5 65.48,17.92 65.5,17.81 65.41,17.75 64.71,17.75 64.71,17.77 64.1,17.77 64.01,17.85 63.09,17.85 63.01,17.77 62.39,17.77 62.39,17.67 62.31,17.67 62.3,17.68 61.94,17.83 61.58,17.66 61.51,17.62 61.43,17.66 61.23,17.8 60.98,17.82 60.89,17.86 60.87,17.96 60.9,18.21 60.79,18.45 60.78,18.48 60.79,18.51 60.63,19.25 59.96,18.9 59.95,18.86 59.83,18.86 59.78,18.81 59.72,18.8 59.69,18.85 59.69,20.27 60.27,20.27 60.27,20.37 60.43,20.37
GND on TOP (solid shape): 31.41,55.39 31.49,55.36 31.79,55.23 32.1,55.31 37.41,55.31 37.49,55.27 37.51,55.19 37.37,54.33 36.09,54.33 36.09,52.39 36.09,52.36 36.06,52.32 36,52.33 35.91,52.43 35.81,52.43 35.75,54.13 35.75,54.33 31.09,54.33 31.09,52.39 31.08,52.32 31.16,52.23 31.16,51.3 30.71,51.3 30.69,51.32 30.69,52.23 30.76,52.32 30.75,52.39 30.75,54.33 30.36,54.33 30.28,54.37 30.26,54.46 30.26,54.67 30.16,54.87 30.15,54.9 30.16,54.94 30.2,54.99 30.24,55.05 30.31,55.1 30.4,55.07 30.47,55.01 30.46,54.98 31.07,54.46 31.3,55.22 31.29,55.26 31.3,55.29 31.34,55.34
GND on TOP (solid shape): 36.73,22.64 36.82,22.58 36.8,22.47 35.89,21.56 35.06,21.56 34.06,20.56 32.78,20.56 31.17,18.95 31.06,18.92 30.99,19.01 29.99,19.01 29.99,17.56 29.49,17.06 28.93,17.06 28.77,17.23 28.75,17.34 28.84,17.4 28.86,17.4 29.02,17.56 29.09,17.56 29.09,17.63 29.11,17.64 29.11,19.2 27.57,19.2 27.34,19.43 27.34,19.47 27.3,19.47 27.21,19.56 27.15,19.56 27.15,20.16 27.18,20.21 27.24,20.2 27.25,20.19 27.72,20.19 27.8,20.15 27.82,20.07 28.29,19.49 28.76,20.07 28.78,20.15 28.86,20.19 29.11,20.19 29.11,20.26 30.99,20.26 30.99,20.72 31.44,20.72 31.76,21.04 32.34,21.04 32.34,21.13 32.44,21.13 32.44,21.63 32.52,21.71 34.58,21.71 34.65,21.79 34.68,21.79 34.95,21.83 35.15,22.01 35.9,22.01 36.53,22.64
GND on TOP (solid shape): 11.38,39.12 11.42,39.21 11.51,39.22 11.62,39.21 11.74,39.22 11.82,39.2 11.86,39.12 11.86,37.09 11.38,36.61 11.38,36.23 11.33,36.23 10.95,35.56 11.71,35.4 11.74,35.41 11.78,35.4 12.5,35.52 12.26,36.21 12.2,36.28 12.23,36.38 12.62,36.78 12.62,36.84 12.69,36.93 12.8,36.91 13.03,36.67 13.03,35.34 12.59,34.9 7.83,34.9 7.74,34.95 7.74,35.05 7.86,35.5 7.72,35.93 7.72,36.04 7.81,36.09 7.98,36.09 8.59,36.7 8.59,37.03 8.71,37.03 8.71,35.53 9.11,35.13 9.94,35.13 10.36,35.55 10.36,36.17 10.75,36.17 11.38,36.8
GND on TOP (solid shape): 78.76,54.81 78.84,54.77 78.86,54.69 78.88,54.39 79.07,54.16 79.09,54.14 79.09,54.12 79.09,52.17 79.37,52.17 79.62,50.68 79.71,50.69 79.75,52.17 79.99,52.17 80.04,52.14 80.03,52.09 79.99,52.05 79.99,48.71 80.08,48.62 80.08,48.51 80.05,48.44 79.98,48.41 79.56,47.73 80.34,47.6 80.42,47.63 80.49,47.6 80.74,47.46 81.02,47.49 81.11,47.48 81.16,47.39 81.16,42.05 81.09,41.95 80.98,41.97 78.45,44.51 78.45,45.91 78.12,46.24 78.12,49.16 78.15,49.24 78.24,49.26 78.32,49.26 78.4,49.26 78.43,49.26 78.46,49.22 78.46,48.93 79.42,48.93 79.42,50.79 78.84,50.79 78.69,50.94 78.69,52.23 78.76,52.32 78.75,52.39 78.75,54.33 78.49,54.33 78.41,54.37 78.39,54.46 78.41,54.57 78.39,54.68 78.41,54.77 78.49,54.81
GND on TOP (solid shape): 46.33,30.17 46.44,30.19 46.51,30.1 46.51,28.05 46.43,27.97 46.37,27.96 46.34,28.01 46.34,28.62 42.58,28.62 42.58,28.02 42.57,28.02 42.28,28.02 41.88,27.62 41.88,26.67 42.75,25.8 42.75,25.63 42.71,25.55 42.62,25.53 42.08,25.33 42.12,24.76 42.14,24.73 42.12,24.7 42.03,24.22 42.4,23.91 42.47,23.86 42.48,23.77 42.45,23.52 42.56,23.29 42.58,23.25 42.56,23.22 42.45,22.85 42.65,22.52 42.69,22.4 42.59,22.33 42.13,22.33 40.5,23.96 39.36,23.96 38.57,23.18 36.31,23.18 35.68,22.54 35.13,22.54 35.1,22.58 35.06,22.62 35.05,22.67 35.1,22.71 35.47,22.71 36.38,23.62 38.62,23.62 39.12,24.12 39.12,26.96 39.17,26.96 39.17,27.18 39.55,27.18 39.55,27.07 39.57,27.05 39.57,26.96 39.66,26.96 39.69,26.92 41.36,26.92 41.68,27.25 41.68,29.84 41.82,29.97 46.13,29.97
GND on TOP (solid shape): outline of 104 points within 79.59,14.96 94.72,24.49
GND on TOP (solid shape): outline of 184 points within 13.49,12.08 28.28,24.85
GND on TOP (solid shape): 81.72,77.69 82.22,77.69 82.3,77.65 82.31,77.55 82.4,76.84 83.07,76.59 83.1,76.6 83.15,76.54 83.06,76.46 83.06,76.39 83.01,76.29 82.9,76.31 81.96,76.29 81.85,75.36 81.86,75.26 81.77,75.2 80.68,75.2 80,74.52 80,73.6 79.83,73.6 79.83,71.64 80,71.64 80,70.91 80.03,70.88 80.05,70.76 79.96,70.7 79.29,70.7 79.2,70.76 79.22,70.88 79.26,70.92 79.26,71.43 79.39,71.56 79.39,71.64 79.43,71.64 79.43,73.6 79.26,73.6 79.26,74.52 78.39,75.39 78.39,75.92 78.46,76.02 78.58,75.97 80.94,75.7 80.7,78.06 80.66,78.18 80.75,78.25 81.16,78.25
GND on TOP (solid shape): 38.85,80.04 38.93,79.94 38.93,79.56 35.06,75.7 35.06,71.01 35.5,70.58 35.5,70.27 35.47,70.23 35.41,70.24 35.35,70.3 35.35,70.32 35.17,70.69 34.76,70.77 34.67,70.79 34.63,70.87 34.63,74.05 34.11,74.58 34.08,74.66 34.12,74.73 34.2,75.47 33.46,75.4 32.19,75.4 31.35,76.24 31.33,76.36 31.43,76.42 32.39,76.55 33.14,77.18 33.22,77.22 33.31,77.18 35.65,76.63 36.39,78.91 36.41,79.02 36.5,79.06 37.76,79.19 38.74,80
GND on TOP (solid shape): 120.23,30.68 120.26,30.73 120.32,30.71 120.36,30.67 122.52,30.67 123.28,29.91 124.4,29.91 124.63,29.68 124.73,29.68 124.82,29.58 124.84,29.45 124.71,29.42 121.53,26.34 125.95,26.42 126.06,26.49 126.15,26.39 126.15,24.7 126.07,24.7 126.04,24.72 126.03,24.76 125.63,25.29 125.08,24.91 125.03,24.84 124.93,24.85 124.3,24.71 124.38,24.07 124.41,23.96 124.32,23.89 123.07,23.89 120.23,26.73
GND on TOP (solid shape): 52.09,27.58 52.2,27.6 52.26,27.51 52.26,22.47 51.17,21.38 49.69,21.38 49.69,21.17 49.17,21.17 48.78,20.79 48.76,20.79 48.38,20.68 48.21,20.32 48.18,20.25 48.11,20.22 47.91,20.22 47.2,20.93 47.19,20.99 47.24,21.02 47.3,21.02 49.02,22.73 49.09,22.76 49.16,22.73 49.3,22.63 49.47,22.59 49.54,22.55 49.57,22.48 49.57,22.33 51.42,22.33 51.42,22.34 51.48,22.34 52.01,22.63 51.83,23.21 51.78,23.29 51.83,23.38 51.96,24.04 51.3,24.18 50,24.18 49.91,24.22 49.9,24.31 49.92,24.36 51.42,24.36 51.42,24.39 51.48,24.39 51.49,24.39 52.08,24.66 51.84,25.27 51.79,25.35 51.82,25.44 51.99,25.77 51.88,26.12 51.86,26.15 51.88,26.18 51.8,26.87 51.11,26.76 50.93,26.76 50.84,26.82 50.86,26.93 51.04,27.11 51.62,27.11
GND on TOP (solid shape): outline of 140 points within 53.17,17.64 68.63,30.34
GND on TOP (solid shape): 126.41,15.69 126.5,15.63 126.49,15.53 126.49,12.95 126.86,12.57 131.05,12.57 131.14,12.53 131.15,12.44 131.12,12.29 131.14,12.13 131.11,12.03 131,12.02 126.12,7.7 132.62,7.44 132.74,7.5 132.82,7.4 132.82,7.1 128.62,2.91 128.51,2.88 128.45,2.98 127.17,3.46 127.87,2.29 127.9,2.29 127.95,2.24 127.88,2.16 126.16,2.16 126.06,2.23 126.45,3.19 125.72,3.75 125.34,3.75 125.1,3.99 125.1,9.77 126.07,10.74 126.07,15.56 126.19,15.69
GND on TOP (solid shape): outline of 90 points within 85.58,70.68 89.83,77.62
GND on TOP (solid shape): outline of 116 points within 107.17,35.71 118.24,45
GND on TOP (solid shape): outline of 112 points within 36.82,59.82 51.11,65.19
GND on TOP (solid shape): outline of 1728 points within 31.78,3.67 91.14,36.83
GND on TOP (solid shape): outline of 2639 points within 3.63,17.35 21.16,69.82
GND on TOP (solid shape): outline of 7308 points within 0.25,0.25 134.82,89.76
GND on BOTTOM (solid shape): 62.42,10.01 61.84,9.42 55.46,9.42 54.82,10.06 54.95,10.19 62.24,10.19
GND on BOTTOM (solid shape): 32.44,22.39 32.4,22.39 32.4,20.59 32.22,20.41 32.01,20.41 32.01,22.39 31.97,22.39 31.97,22.64 32.44,22.64
GND on BOTTOM (solid shape): 22.01,50.54 21.71,50.54 21.32,50.15 21.28,50.19 21.27,50.22 21.27,51.46 21.62,51.81 21.62,52.08 22.01,52.08
GND on BOTTOM (solid shape): 99.33,38.11 99.15,37.93 97.91,37.93 97.35,38.5 97.33,38.61 97.42,38.67 98.77,38.67
GND on BOTTOM (solid shape): 17.86,27.66 17.34,27.14 17.34,25.12 17.27,25.03 17.16,25.05 16.85,25.36 16.85,27.4 17.19,27.74 17.86,27.74
GND on BOTTOM (solid shape): 27.98,17.87 27.98,14.57 25.59,14.57 25.11,15.05 25.11,18.35 24.9,18.56 24.87,18.67 24.97,18.73 27.12,18.73
GND on BOTTOM (solid shape): 28.77,10.25 28.77,10.11 28.73,10.07 28.68,10.08 26.08,12.68 26.07,12.73 26.12,12.76 26.25,12.76
GND on BOTTOM (solid shape): 77.45,12.75 77.5,12.76 77.53,12.72 77.53,12.63 70.55,5.65 70.47,5.65 70.42,5.68 70.43,5.74
GND on BOTTOM (solid shape): 64.85,17.72 64.94,17.65 64.92,17.54 63.87,16.5 63.24,16.5 63.03,16.29 62.93,16.3 62.88,16.35 64.25,17.72
GND on BOTTOM (solid shape): 50.12,12.59 50.08,12.5 49.49,12.5 49.14,12.14 46.8,12.14 46.71,12.2 46.73,12.31 46.8,12.39 46.8,12.65 50.12,12.65
GND on BOTTOM (solid shape): 22.12,21.76 22.23,21.79 22.29,21.69 22.29,18.51 23.43,17.36 23.43,17.23 23.4,17.18 23.34,17.19 22.06,18.47 22.06,21.71
GND on BOTTOM (solid shape): 22.85,21.71 22.96,21.73 23.03,21.64 23.03,18.79 24.04,17.77 24.04,17.63 24.01,17.59 23.95,17.6 22.82,18.73 22.82,21.68
GND on BOTTOM (solid shape): 35.11,56.07 35.22,56.09 35.28,55.99 35.28,55.66 31.38,51.76 31.27,51.73 31.2,51.83 31.2,52.16
GND on BOTTOM (solid shape): 51.02,30.3 51.05,30.34 51.1,30.33 52.54,28.89 55.85,28.89 56.15,28.58 56.18,28.47 56.08,28.41 52.77,28.41 51.02,30.16
GND on BOTTOM (solid shape): 67.49,65.62 67.58,65.56 67.56,65.45 65.29,63.17 65.18,63.15 65.11,63.25 65.11,63.59 67.14,65.62
GND on BOTTOM (solid shape): 68.66,67.55 68.75,67.49 68.73,67.38 67.5,66.15 67.13,66.15 67.04,66.22 67.06,66.33 68.28,67.55
GND on BOTTOM (solid shape): 68.87,76.85 68.92,76.82 68.91,76.77 67.36,75.22 67.25,75.2 67.19,75.3 67.19,75.74 67.47,76.03 67.98,76.03 68.8,76.85
GND on BOTTOM (solid shape): 70.9,19.51 70.99,19.44 70.97,19.33 70.63,19 62.4,19 62.31,19.06 62.33,19.17 62.67,19.51
GND on BOTTOM (solid shape): 73.93,52.47 74.04,52.49 74.1,52.4 74.1,51.62 72.31,49.83 72.26,49.82 72.22,49.86 72.22,50 73.62,51.4 73.62,52.16
GND on BOTTOM (solid shape): 124.04,55.83 124.1,55.92 124.21,55.9 126.43,53.69 126.43,53.29 126.37,53.2 126.26,53.22 124.04,55.43
GND on BOTTOM (solid shape): 21.35,56.06 21.46,56.09 21.53,55.99 21.53,55.21 22,54.74 22,54.36 19.67,54.36 19.6,54.42 19.59,54.48 19.64,54.51 19.8,54.51
GND on BOTTOM (solid shape): 53.05,32.08 53.11,32.17 53.22,32.15 53.69,31.69 56.1,31.69 56.41,31.38 56.43,31.27 56.34,31.2 53.65,31.2 53.05,31.81
GND on BOTTOM (solid shape): 71.52,42.31 71.63,42.33 71.69,42.24 71.69,40.88 69.41,38.59 69.41,38.29 69.1,37.98 68.99,37.96 68.92,38.05 68.92,39.72
GND on BOTTOM (solid shape): 101.93,66.87 102.02,66.8 102,66.69 101.57,66.26 97.97,66.26 97.88,66.32 97.9,66.43 98.21,66.74 101.13,66.74 101.26,66.87
GND on BOTTOM (solid shape): 38.05,65.78 38.05,65.32 37.99,65.23 37.88,65.25 35.94,67.18 30.96,67.18 30.88,67.22 30.86,67.3 30.87,67.39 32.04,67.39 32.29,67.64 36.19,67.64
